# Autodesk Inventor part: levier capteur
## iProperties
Created: 2007-07
Part Number: levier capteur
Document SubType Name: Modeling
Designer: EF
Density: 1 g/cm^3
Author: EF
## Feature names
1. Extrusion1
